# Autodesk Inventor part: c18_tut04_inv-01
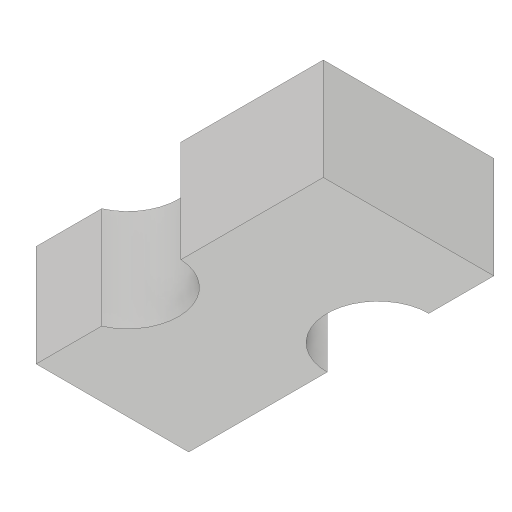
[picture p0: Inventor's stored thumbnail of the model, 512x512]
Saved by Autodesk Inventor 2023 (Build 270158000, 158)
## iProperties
Created: 2017-06
Part Number: c18_tut04_inv-01
Material: Generic
Document SubType Name: Modeling
Designer: CADCIM 00
Density: 1 g/cm^3
Appearance: Default
Author: CADCIM 00
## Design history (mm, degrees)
derived "c18_tut04_inv.ipt"
feature "Solid1::c18_tut04_inv.ipt"
tag "TaggingFeature1"
body "Solid1"
other parameters: "d2" = 16.66667, "d3" = 33.33333, "d4" = 0, "RAD" = 16.66667, "EXT" = 33.33333
